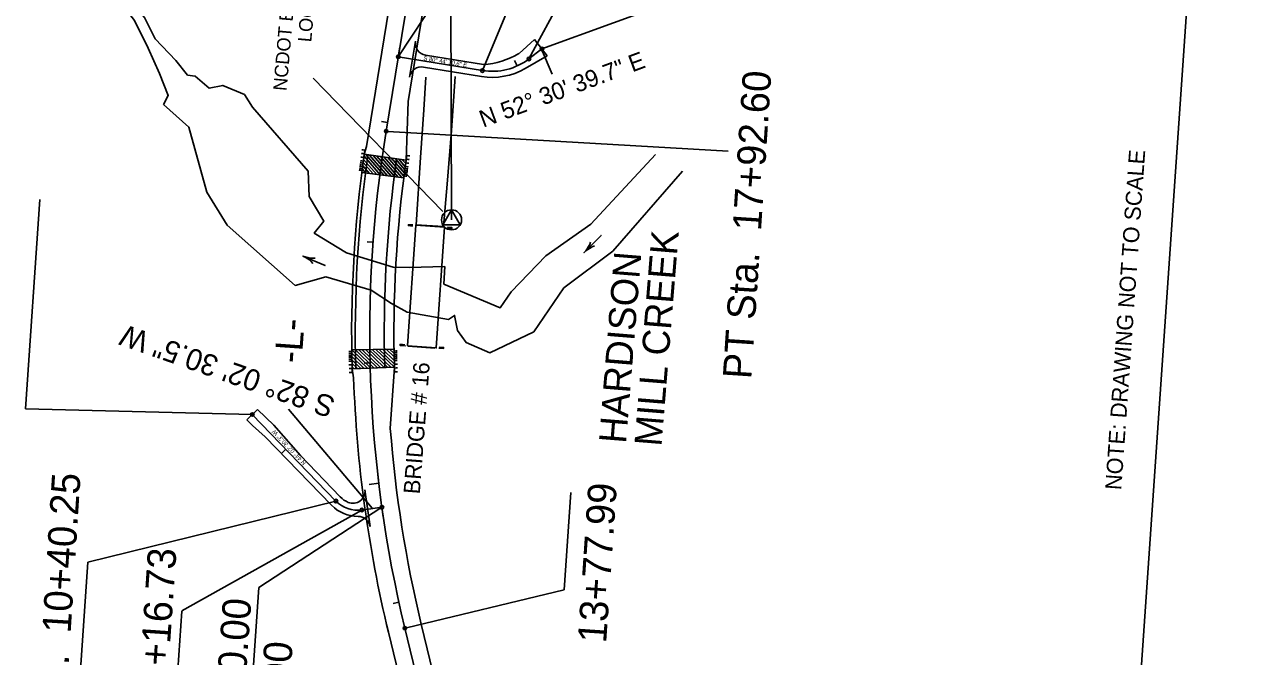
# Model space of a CAD drawing. Extents: x 2599057 to 2600057, y 728628 to 732947.
# Drawn here: x 2599397 to 2600057, y 732014 to 732354 of the extents above; entities that cross this region are included whole.
import ezdxf

# ---------------------------------------------------------------- set-up
doc = ezdxf.new("R2010")
doc.units = 0
for name, color, linetype in [('CTL NGS Horizontal and Vertical CELL', 7, 'Continuous'), ('CTL NGS Horizontal and Vertical Leader', 7, 'Continuous'), ('CTL NGS Horizontal and Vertical Text', 7, 'Continuous'), ('CTL NGS Horizontal CELL', 7, 'Continuous'), ('CTL Sheet Border CELL', 7, 'Continuous'), ('Exist Hydro River Flow Arrow CELL', 7, 'Continuous'), ('Exist Roads EOP', 7, 'Continuous'), ('Exist Structure Major Bridge WW', 7, 'Continuous'), ('Exist Structure Major Deck Tunnel Box Culvert', 7, 'Continuous'), ('Old_Level_25', 7, 'Continuous'), ('Old_Level_30', 7, 'Continuous'), ('Old_Level_55', 7, 'Continuous'), ('Prop DGN Element Guardrail', 7, 'Continuous'), ('Prop EOT', 7, 'Continuous'), ('Prop Horizontal Alignment', 7, 'Continuous'), ('Prop Horizontal Alignment Direction Label', 7, 'Continuous'), ('Prop Horizontal Alignment Station Label', 7, 'Continuous'), ('Prop Horizontal Alignment Tick Large', 7, 'Continuous'), ('Prop Horizontal Alignment Tick Small', 7, 'Continuous'), ('Prop Lane Lines', 7, 'Continuous'), ('Prop Roadway Bridge', 7, 'Continuous'), ('Prop Structure Anchor Unit CELL', 7, 'Continuous')]:
    doc.layers.add(name, color=color, linetype=linetype)

# ---------------------------------------------------------------- blocks, each defined once
blk = doc.blocks.new('CTL NGS HORIZONTAL AND VERTICAL')
at = {"layer": 'CTL NGS Horizontal and Vertical CELL'}
blk.add_line((0, 0), (0, 0), dxfattribs=at)
blk.add_lwpolyline([(-0.0638, -0.0372), (0.0638, -0.0372), (0, 0.0737)], close=True, dxfattribs=at)
blk.add_circle((0, -0.0001), 0.0738, dxfattribs=at)
blk = doc.blocks.new('EXIST HYDRO RIVER FLOW ARROW')
at = {"layer": 'Exist Hydro River Flow Arrow CELL'}
blk.add_line((0, 0), (0, 0), dxfattribs=at)
blk.add_lwpolyline([(0, 0.04575), (0.03775, 0.03), (0.07725, 0.01725), (0.118, 0.00775), (0.159, 0.0015), (0.2, 0), (-0.2, 0), (0.2, 0), (0.159, -0.0015), (0.118, -0.00775), (0.07725, -0.01725), (0.03775, -0.03), (0, -0.04575)], dxfattribs=at)

msp = doc.modelspace()

# ---------------------------------------------------------------- linework, layer by layer
at = {"layer": 'CTL NGS Horizontal and Vertical Leader'}
msp.add_lwpolyline([(2599621.88, 732253.44), (2599552.09, 732325.29)], dxfattribs=at)
at = {"layer": 'CTL NGS Horizontal CELL'}
msp.add_line((2599626.5, 732249.03), (2599625.22, 732762.37), dxfattribs=at)
at = {"layer": 'CTL Sheet Border CELL'}
msp.add_lwpolyline([(2599146.23, 732931.19), (2599056.61, 731629.92), (2599967.49, 731567.19), (2600057.11, 732868.45)], close=True, dxfattribs=at)
at = {"layer": 'Exist Roads EOP'}
for p, q in [((2599607.4, 732246.37), (2599622.04, 732245.43)), ((2599603.21, 732180.98), (2599617.53, 732179.94))]:
    msp.add_line(p, q, dxfattribs=at)
for points in [[(2599607.4, 732246.37), (2599609.74, 732282.66), (2599611.51, 732308.16), (2599612.71, 732325.75)], [(2599628.39, 732326.14), (2599626.41, 732297.06), (2599624.17, 732268.3), (2599622.09, 732245.51)]]:
    msp.add_lwpolyline(points, dxfattribs=at)
at = {"layer": 'Exist Structure Major Bridge WW'}
for points in [[(2599605.69, 732245.75), (2599604.46, 732245.88), (2599603.23, 732245.93), (2599603.25, 732246.41), (2599604.52, 732246.35), (2599605.74, 732246.28)], [(2599624.19, 732244.49), (2599625.38, 732244.43), (2599626.66, 732244.32), (2599626.7, 732244.83), (2599625.44, 732244.91), (2599624.25, 732245)], [(2599601.24, 732181.23), (2599600.03, 732181.32), (2599598.75, 732181.46), (2599598.79, 732181.94), (2599600.07, 732181.83), (2599601.28, 732181.72)], [(2599619.72, 732179.99), (2599620.93, 732179.9), (2599622.18, 732179.84), (2599622.25, 732180.32), (2599620.98, 732180.37), (2599619.77, 732180.48)]]:
    msp.add_lwpolyline(points, dxfattribs=at)
at = {"layer": 'Exist Structure Major Deck Tunnel Box Culvert'}
for points in [[(2599602.73, 732181.22), (2599618.24, 732180.08), (2599622.73, 732245.07), (2599607.21, 732246.21), (2599602.73, 732181.22)], [(2599601.79, 732181.22), (2599601.82, 732181.22)]]:
    msp.add_lwpolyline(points, dxfattribs=at)
at = {"layer": 'Old_Level_55'}
for p, q in [((2599736.31, 732284.19), (2599701.55, 732246.73)), ((2599736.31, 732284.19), (2599701.55, 732246.73)), ((2599701.55, 732246.73), (2599677.31, 732229.62)), ((2599701.55, 732246.73), (2599677.31, 732229.62)), ((2599677.31, 732229.62), (2599658.62, 732210.35)), ((2599603.69, 732223.44), (2599622.81, 732223.83)), ((2599603.69, 732223.44), (2599622.81, 732223.83)), ((2599603.69, 732223.44), (2599622.81, 732223.83)), ((2599622.35, 732214.35), (2599622.81, 732223.83)), ((2599622.35, 732214.35), (2599622.81, 732223.83)), ((2599622.35, 732214.35), (2599622.81, 732223.83))]:
    msp.add_line(p, q, dxfattribs=at)
for points in [[(2599392.02, 732437.31), (2599398.33, 732426.52), (2599412.37, 732410.63), (2599427.82, 732398.95), (2599438.1, 732388.17), (2599445.41, 732378.83), (2599453.3, 732367.44), (2599461.18, 732357.95), (2599466.9, 732346.47), (2599478, 732334.86), (2599484.4, 732326.82), (2599488.48, 732326.29)], [(2599389.53, 732424.82), (2599401.21, 732411.85), (2599408.88, 732405.13), (2599423.25, 732392.7), (2599433.36, 732381.72), (2599440.68, 732373.69), (2599449.5, 732364.36), (2599455.83, 732356.26), (2599463.11, 732341.45), (2599469.26, 732327.75), (2599474.01, 732316.01), (2599471.41, 732311.09)], [(2599603.69, 732223.44), (2599595.14, 732223.5), (2599569.92, 732231.34), (2599552.61, 732241.9), (2599557.69, 732248.32), (2599549.81, 732261.66), (2599549.24, 732275.13), (2599519.31, 732309.74), (2599514.95, 732316.48), (2599503.29, 732321.39), (2599495.93, 732319.88), (2599488.48, 732326.29)], [(2599603.69, 732223.44), (2599595.14, 732223.5), (2599569.92, 732231.34), (2599552.61, 732241.9), (2599557.69, 732248.32), (2599549.81, 732261.66), (2599549.24, 732275.13), (2599519.31, 732309.74), (2599514.95, 732316.48), (2599503.29, 732321.39), (2599495.93, 732319.88), (2599488.48, 732326.29)], [(2599602.68, 732199.29), (2599594.17, 732203.9), (2599583.3, 732211.09), (2599558.78, 732218.35), (2599542.31, 732213.76), (2599505.67, 732246.16), (2599494.71, 732263.98), (2599485.03, 732298.96), (2599471.41, 732311.09)], [(2599602.68, 732199.29), (2599594.17, 732203.9), (2599583.3, 732211.09), (2599558.78, 732218.35), (2599542.31, 732213.76), (2599505.67, 732246.16), (2599494.71, 732263.98), (2599485.03, 732298.96), (2599471.41, 732311.09)], [(2599750.74, 732275.15), (2599713.4, 732232.16), (2599686.93, 732212.39), (2599670.71, 732188.7), (2599647.04, 732177.46), (2599634.29, 732183.06), (2599629.76, 732189.38), (2599628.14, 732197.56), (2599624.87, 732195.41), (2599602.68, 732199.29)], [(2599677.31, 732229.62), (2599658.62, 732210.35), (2599652.74, 732201.73), (2599622.35, 732214.35)]]:
    msp.add_lwpolyline(points, dxfattribs=at)
at = {"layer": 'Prop DGN Element Guardrail'}
for p, q in [((2599578.21, 732274.5), (2599579.83, 732286.58)), ((2599600.77, 732271.63), (2599602.4, 732283.7))]:
    msp.add_line(p, q, dxfattribs=at)
at = {"layer": 'Prop EOT'}
for p, q in [((2599624.95, 732559.69), (2599580.73, 732288.53)), ((2599603.11, 732312.74), (2599642.92, 732556.76)), ((2599603.94, 732325.9), (2599607.08, 732345.14)), ((2599662.81, 732338.48), (2599671.21, 732346.17)), ((2599671.21, 732346.17), (2599678.03, 732337.26)), ((2599612.45, 732337.68), (2599643.64, 732332.59)), ((2599678.03, 732337.26), (2599666.13, 732330.44)), ((2599642.6, 732326.18), (2599611.41, 732331.26)), ((2599602.05, 732281.1), (2599603.11, 732312.74)), ((2599580.73, 732288.53), (2599579.53, 732284.3)), ((2599579.53, 732284.3), (2599602.05, 732281.1)), ((2599572.99, 732168.82), (2599595.72, 732169.66)), ((2599573.79, 732163.95), (2599572.99, 732168.82)), ((2599595.72, 732169.66), (2599593.54, 732136.67)), ((2599521.97, 732146.9), (2599516.26, 732141.37)), ((2599530.85, 732138.49), (2599521.97, 732146.9)), ((2599516.26, 732141.37), (2599519.27, 732138.38)), ((2599519.27, 732138.38), (2599526.24, 732132.28)), ((2599545.13, 732122.09), (2599530.85, 732138.49)), ((2599526.24, 732132.28), (2599561.94, 732095.36)), ((2599566.62, 732099.88), (2599545.13, 732122.09)), ((2599582.63, 732083.91), (2599579.87, 732103.74)), ((2599610.21, 732031.35), (2599633.56, 731934.69)), ((2599615.86, 731930.42), (2599592.52, 732027.08))]:
    msp.add_line(p, q, dxfattribs=at)
for centre, radius, start, end in [((2599613.5, 732344.09), 6.5, 170.73628, 260.73628), ((2599640.66, 732376.4), 43.91, 273.89697, 300.29039), ((2599610.36, 732324.85), 6.5, 80.73628, 170.73628), ((2599648.35, 732361.46), 35.75, 260.73628, 299.81004), ((2600258.47, 732187.92), 685.1, 182.0052, 193.57808), ((2600258.47, 732187.92), 666.9, 184.40802, 193.57808), ((2599573.42, 732102.94), 6.5, 246.9931, 7.07201), ((2599575.96, 732108.92), 19.5, 224.04174, 270.53059), ((2599575.96, 732108.92), 13, 224.04174, 246.9931), ((2599576.2, 732082.92), 6.5, 8.74938, 90.53059)]:
    msp.add_arc(centre, radius, start, end, dxfattribs=at)
at = {"layer": 'Prop Horizontal Alignment'}
for p, q in [((2599591.29, 732296.74), (2599633.93, 732558.22)), ((2599668.13, 732335.67), (2599675.14, 732341.04)), ((2599597.81, 732336.77), (2599643.12, 732329.38)), ((2599564.28, 732097.62), (2599519.21, 732144.23)), ((2599588.98, 732094.33), (2599578.21, 732092.82)), ((2599628.52, 731916.76), (2599601.36, 732029.22))]:
    msp.add_line(p, q, dxfattribs=at)
for centre, radius, start, end in [((2599648.35, 732361.46), 32.5, 260.73628, 307.48897), ((2600258.47, 732187.92), 676, 170.73628, 193.57808), ((2599575.96, 732108.92), 16.25, 224.04174, 277.9582)]:
    msp.add_arc(centre, radius, start, end, dxfattribs=at)
at = {"layer": 'Prop Horizontal Alignment Station Label'}
for p, q in [((2599643.12, 732329.38), (2599691.64, 732446.56)), ((2599597.81, 732336.77), (2599664.81, 732438.57)), ((2599668.13, 732335.67), (2599719.29, 732430.71)), ((2599675.14, 732341.04), (2599757.17, 732370.9)), ((2599680.67, 732327.5), (2599674.87, 732340.84)), ((2599592.25, 732296.59), (2599775.32, 732286.05)), ((2599397.18, 732147.29), (2599404.93, 732259.88)), ((2599397.18, 732147.29), (2599519.21, 732144.23)), ((2599583.77, 732093.75), (2599538.78, 732147.09)), ((2599687.18, 732049.94), (2599690.79, 732102.25)), ((2599430.7, 732064.68), (2599564.28, 732097.62)), ((2599481.29, 732038.48), (2599578.21, 732092.82)), ((2599588.98, 732094.33), (2599522.7, 732051.2)), ((2599430.7, 732064.68), (2599426.11, 731998.03)), ((2599522.7, 732051.2), (2599514.56, 731932.05)), ((2599602.31, 732029.45), (2599687.18, 732049.94)), ((2599481.24, 732038.45), (2599476.66, 731971.96))]:
    msp.add_line(p, q, dxfattribs=at)
for centre in [(2599675.14, 732341.04), (2599597.81, 732336.77), (2599668.13, 732335.67), (2599643.12, 732329.38), (2599591.29, 732296.74), (2599519.21, 732144.23), (2599564.28, 732097.62), (2599588.98, 732094.33), (2599578.21, 732092.82), (2599601.36, 732029.22)]:
    msp.add_circle(centre, 0.975, dxfattribs=at)
at = {"layer": 'Prop Horizontal Alignment Tick Large'}
for p, q in [((2599597.81, 732336.77), (2599598.65, 732341.91)), ((2599586.56, 732113.68), (2599587.13, 732108.51)), ((2599587.3, 732107.22), (2599582.14, 732106.6)), ((2599588.98, 732094.33), (2599589.7, 732089.18))]:
    msp.add_line(p, q, dxfattribs=at)
at = {"layer": 'Prop Horizontal Alignment Tick Small'}
for p, q in [((2599661.78, 732331.86), (2599660.44, 732334.82)), ((2599592.06, 732301.49), (2599588.85, 732302.01)), ((2599584.25, 732236.99), (2599581.01, 732237.22)), ((2599582.66, 732172.03), (2599579.41, 732171.95)), ((2599537.28, 732125.54), (2599534.95, 732123.28)), ((2599598.15, 732043.16), (2599594.98, 732042.46))]:
    msp.add_line(p, q, dxfattribs=at)
at = {"layer": 'Prop Lane Lines'}
for radius, end in [(683.8, 181.59491), (668.2, 181.58253)]:
    msp.add_arc((2600258.47, 732187.92), radius, 171.92077, end, dxfattribs=at)
at = {"layer": 'Prop Roadway Bridge'}
for p, q in [((2599586.2, 732273.48), (2599579.15, 732281.57)), ((2599588.14, 732273.23), (2599579.39, 732283.28)), ((2599590.08, 732272.99), (2599580.32, 732284.19)), ((2599592.01, 732272.74), (2599582.29, 732283.91)), ((2599593.95, 732272.49), (2599584.25, 732283.63)), ((2599595.89, 732272.25), (2599586.22, 732283.35)), ((2599597.83, 732272), (2599588.19, 732283.07)), ((2599599.77, 732271.75), (2599590.16, 732282.79)), ((2599600.88, 732272.46), (2599592.12, 732282.51)), ((2599601.11, 732274.17), (2599594.09, 732282.23)), ((2599601.34, 732275.89), (2599596.06, 732281.95)), ((2599601.57, 732277.6), (2599598.03, 732281.67)), ((2599601.8, 732279.31), (2599599.99, 732281.39)), ((2599602, 732280.74), (2599601.68, 732281.15)), ((2599600.77, 732271.63), (2599578.21, 732274.5)), ((2599580.38, 732274.22), (2599578.46, 732276.43)), ((2599582.32, 732273.97), (2599578.69, 732278.14)), ((2599584.26, 732273.73), (2599578.92, 732279.85)), ((2599572.78, 732179.12), (2599595.52, 732179.41)), ((2599583.07, 732169.19), (2599572.78, 732179.08)), ((2599581.27, 732169.13), (2599572.8, 732177.25)), ((2599579.46, 732169.06), (2599572.83, 732175.42)), ((2599584.88, 732169.26), (2599574.59, 732179.14)), ((2599586.69, 732169.33), (2599576.44, 732179.17)), ((2599588.49, 732169.39), (2599578.29, 732179.19)), ((2599590.3, 732169.46), (2599580.14, 732179.21)), ((2599592.11, 732169.53), (2599582, 732179.24)), ((2599593.91, 732169.59), (2599583.85, 732179.26)), ((2599595.72, 732169.66), (2599585.7, 732179.29)), ((2599595.67, 732171.51), (2599587.55, 732179.31)), ((2599595.63, 732173.35), (2599589.4, 732179.33)), ((2599595.59, 732175.19), (2599591.26, 732179.36)), ((2599595.56, 732177.03), (2599593.11, 732179.38)), ((2599595.53, 732178.86), (2599594.96, 732179.4)), ((2599577.65, 732168.99), (2599572.87, 732173.58)), ((2599575.85, 732168.92), (2599572.91, 732171.74)), ((2599574.04, 732168.86), (2599572.96, 732169.9))]:
    msp.add_line(p, q, dxfattribs=at)
for radius, end in [(685.75, 181.59642), (663, 181.57827)]:
    msp.add_arc((2600258.47, 732187.92), radius, 171.92077, end, dxfattribs=at)
at = {"layer": 'Prop Structure Anchor Unit CELL'}
for p, q in [((2599578.49, 732286.38), (2599578.59, 732287.12)), ((2599577.68, 732280.34), (2599577.78, 732281.08)), ((2599579.02, 732280.54), (2599577.73, 732280.71)), ((2599577.95, 732282.35), (2599578.05, 732283.09)), ((2599579.29, 732282.55), (2599578, 732282.72)), ((2599578.21, 732274.5), (2599579.83, 732286.58)), ((2599578.22, 732284.37), (2599578.32, 732285.11)), ((2599579.56, 732284.56), (2599578.27, 732284.74)), ((2599579.83, 732286.58), (2599578.54, 732286.75)), ((2599600.77, 732271.63), (2599602.4, 732283.7)), ((2599602.13, 732281.69), (2599603.42, 732281.52)), ((2599602.4, 732283.7), (2599603.69, 732283.53)), ((2599603.37, 732281.15), (2599603.47, 732281.89)), ((2599603.64, 732283.16), (2599603.74, 732283.9)), ((2599577, 732275.31), (2599577.1, 732276.05)), ((2599578.34, 732275.5), (2599577.05, 732275.68)), ((2599577.14, 732276.31), (2599577.24, 732277.05)), ((2599578.48, 732276.51), (2599577.19, 732276.68)), ((2599577.27, 732277.32), (2599577.37, 732278.06)), ((2599578.61, 732277.52), (2599577.32, 732277.69)), ((2599577.41, 732278.33), (2599577.51, 732279.07)), ((2599578.75, 732278.52), (2599577.46, 732278.7)), ((2599577.55, 732279.33), (2599577.65, 732280.07)), ((2599578.88, 732279.53), (2599577.6, 732279.7)), ((2599601.05, 732273.64), (2599602.33, 732273.46)), ((2599601.18, 732274.64), (2599602.47, 732274.47)), ((2599601.32, 732275.65), (2599602.6, 732275.48)), ((2599601.45, 732276.66), (2599602.74, 732276.48)), ((2599601.59, 732277.66), (2599602.88, 732277.49)), ((2599601.86, 732279.68), (2599603.15, 732279.5)), ((2599602.28, 732273.1), (2599602.38, 732273.83)), ((2599602.42, 732274.1), (2599602.52, 732274.84)), ((2599602.55, 732275.11), (2599602.65, 732275.85)), ((2599602.69, 732276.12), (2599602.79, 732276.85)), ((2599602.83, 732277.12), (2599602.93, 732277.86)), ((2599603.1, 732279.14), (2599603.2, 732279.87)), ((2599600.91, 732272.63), (2599602.2, 732272.46)), ((2599602.15, 732272.09), (2599602.25, 732272.83)), ((2599571.49, 732178.45), (2599571.5, 732177.71)), ((2599572.8, 732178.1), (2599571.5, 732178.08)), ((2599571.51, 732177.43), (2599571.53, 732176.69)), ((2599572.82, 732177.09), (2599571.52, 732177.06)), ((2599571.53, 732176.42), (2599571.55, 732175.67)), ((2599572.84, 732176.07), (2599571.54, 732176.05)), ((2599571.55, 732175.4), (2599571.57, 732174.66)), ((2599572.86, 732175.06), (2599571.56, 732175.03)), ((2599572.78, 732179.12), (2599573.02, 732166.93)), ((2599595.52, 732179.41), (2599595.77, 732167.23)), ((2599595.54, 732178.4), (2599596.84, 732178.42)), ((2599595.57, 732177.38), (2599596.86, 732177.41)), ((2599595.59, 732176.37), (2599596.89, 732176.39)), ((2599595.61, 732175.35), (2599596.91, 732175.38)), ((2599596.84, 732178.79), (2599596.85, 732178.05)), ((2599596.86, 732177.78), (2599596.87, 732177.04)), ((2599596.88, 732176.76), (2599596.89, 732176.02)), ((2599596.9, 732175.75), (2599596.91, 732175)), ((2599596.92, 732174.73), (2599596.93, 732173.99)), ((2599571.57, 732174.39), (2599571.59, 732173.64)), ((2599572.88, 732174.04), (2599571.58, 732174.02)), ((2599571.59, 732173.37), (2599571.61, 732172.63)), ((2599572.9, 732173.03), (2599571.6, 732173)), ((2599571.63, 732171.34), (2599571.65, 732170.6)), ((2599572.94, 732171), (2599571.64, 732170.97)), ((2599571.68, 732169.31), (2599571.69, 732168.57)), ((2599572.98, 732168.97), (2599571.68, 732168.94)), ((2599595.63, 732174.33), (2599596.93, 732174.36)), ((2599595.65, 732173.32), (2599596.95, 732173.35)), ((2599595.69, 732171.29), (2599596.99, 732171.31)), ((2599595.73, 732169.26), (2599597.03, 732169.28)), ((2599596.94, 732173.72), (2599596.95, 732172.97)), ((2599596.98, 732171.69), (2599597, 732170.94)), ((2599597.02, 732169.66), (2599597.04, 732168.91)), ((2599571.72, 732167.28), (2599571.73, 732166.54)), ((2599573.02, 732166.93), (2599571.72, 732166.91)), ((2599595.77, 732167.23), (2599597.07, 732167.25)), ((2599597.06, 732167.63), (2599597.08, 732166.88))]:
    msp.add_line(p, q, dxfattribs=at)

# ---------------------------------------------------------------- block references
at = {"layer": 'CTL NGS Horizontal and Vertical CELL', "xscale": 73.12499999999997, "yscale": 73.12499999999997}
msp.add_blockref('CTL NGS HORIZONTAL AND VERTICAL', (2599626.5, 732249.03), dxfattribs=at)
at = {"layer": 'Exist Hydro River Flow Arrow CELL', "xscale": 32.499999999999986}
for p, yscale, rotation in [((2599702.42, 732235.99), 32.499999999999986, -134.77736536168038), ((2599552.47, 732226.95), 32.49999999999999, 156.54445895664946)]:
    msp.add_blockref('EXIST HYDRO RIVER FLOW ARROW', p, dxfattribs=dict(at, yscale=yscale, rotation=rotation))

# ---------------------------------------------------------------- texts
at = {"layer": 'CTL NGS Horizontal and Vertical Text'}
for s, p in [('NCDOT BASELINE STATION "BL-3"', (2599537.7, 732318.22)), ('LOCALIZED CORDINATES', (2599550.97, 732344.46))]:
    msp.add_text(s, height=7.3125, rotation=85.0629, dxfattribs=at).set_placement(p)
at = {"layer": 'CTL Sheet Border CELL'}
msp.add_text('NOTE: DRAWING NOT TO SCALE', height=8.6956, rotation=85.95485, dxfattribs=at).set_placement((2599987.02, 732103.39))
at = {"layer": 'Old_Level_25'}
msp.add_text('BRIDGE # 16', height=8.775, rotation=85.60476, dxfattribs=at).set_placement((2599609.37, 732101.16))
at = {"layer": 'Old_Level_30'}
for s, p in [('MILL CREEK', (2599739.48, 732126.76)), ('HARDISON', (2599720.38, 732128.31))]:
    msp.add_text(s, height=14.625, rotation=85.37425, dxfattribs=at).set_placement(p)
at = {"layer": 'Prop Horizontal Alignment Direction Label'}
for s, height, rotation, p in [('S 80%%d 44\' 10.6" E', 2.275, 350.73628, (2599611.24, 732335.01)), ('N 52%%d 30\' 39.7" E', 9.2137, 20.34453, (2599643.52, 732298.59)), ('S 82%%d 02\' 30.5" W', 11.5172, 160.74062, (2599564.69, 732153.06)), ('N 44%%d 02\' 30.3" W', 2.275, 133.61146, (2599548.32, 732118.28))]:
    msp.add_text(s, height=height, rotation=rotation, dxfattribs=at).set_placement(p)
at = {"layer": 'Prop Horizontal Alignment Station Label'}
for s, height, rotation, p in [('PT Sta.  17+92.60', 15.3562, 86.23234, (2599787.81, 732163.06)), ('-L-', 14.625, 85.97728, (2599545.75, 732171.53)), ('PT Sta.  10+40.25', 15.3562, 86.39949, (2599416.41, 731946.57)), ('PC Sta.  13+77.99', 15.3562, 86.12174, (2599704.16, 731938.95)), ('PC Sta.  10+16.73', 15.3562, 86.10131, (2599467.04, 731903.89)), ('DR1 POT Sta.  10+00.00', 15.3562, 85.82461, (2599502.15, 731816.56)), ('-L- POC Sta.  14+80.00', 15.3562, 85.82461, (2599525.42, 731806.96))]:
    msp.add_text(s, height=height, rotation=rotation, dxfattribs=at).set_placement(p)

doc.saveas('drawing.dxf')
